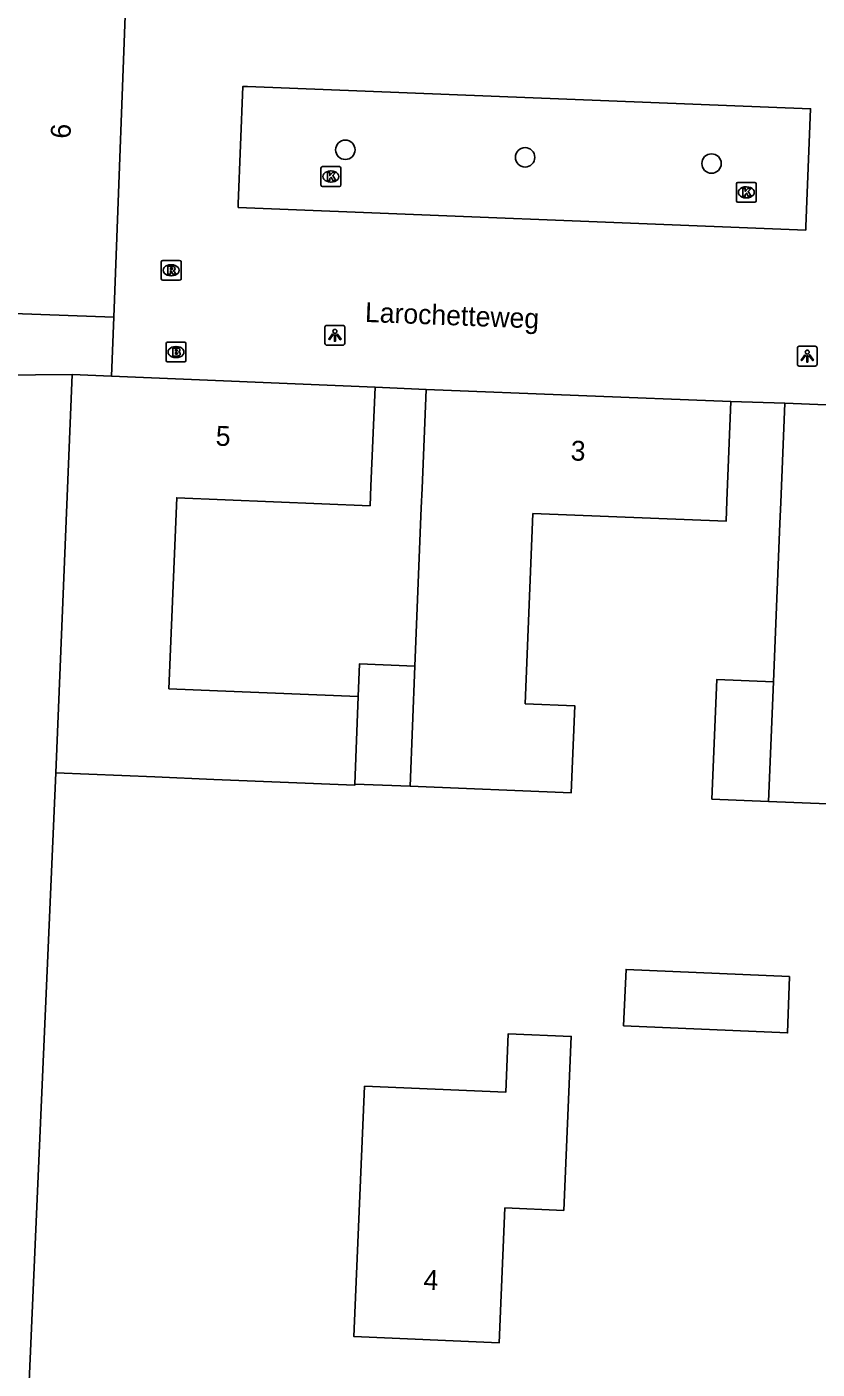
# Model space of a CAD drawing. Extents: x 160787 to 161428, y 386828 to 387483.
# Drawn here: x 160869.9 to 160909.7, y 387090.3 to 387157.9 of the extents above; entities that cross this region are included whole.
import ezdxf

# ---------------------------------------------------------------- set-up
doc = ezdxf.new("R2010")
doc.units = 0
for name, color, linetype in [('IMGEO_Boom', 7, 'Continuous'), ('IMGEO_Brandkraan', 7, 'Continuous'), ('IMGEO_Groenvoorziening', 7, 'Continuous'), ('IMGEO_Kolk', 7, 'Continuous'), ('IMGEO_Lichtpunt', 7, 'Continuous'), ('IMGEO_Openbare_ruimte_label', 7, 'Continuous'), ('IMGEO_Pand', 7, 'Continuous'), ('IMGEO_Pand_nummerreeks', 7, 'Continuous'), ('IMGEO_Rijbaan_lokaal_open', 7, 'Continuous'), ('IMGEO_Rioolput', 7, 'Continuous'), ('IMGEO_Voetpad_open', 7, 'Continuous')]:
    doc.layers.add(name, color=color, linetype=linetype)

msp = doc.modelspace()

# ---------------------------------------------------------------- linework, layer by layer
at = {"layer": 'IMGEO_Boom'}
for centre in [(160885.959, 387151.72), (160895.014, 387151.341), (160904.402, 387151.03)]:
    msp.add_circle(centre, 0.489, dxfattribs=at)
at = {"layer": 'IMGEO_Brandkraan'}
for p, q in [((160877.007, 387142.028), (160877.859, 387142.028)), ((160876.932, 387141.102), (160876.932, 387141.954)), ((160877.42, 387141.808), (160877.445, 387141.808)), ((160877.933, 387141.954), (160877.933, 387141.102)), ((160877.859, 387141.028), (160877.007, 387141.028)), ((160877.443, 387141.248), (160877.418, 387141.248))]:
    msp.add_line(p, q, dxfattribs=at)
for points in [[(160877.007, 387142.028), (160877.859, 387142.028)], [(160876.932, 387141.102), (160876.932, 387141.954)], [(160877.28, 387141.728), (160877.28, 387141.328), (160877.493, 387141.328)], [(160877.511, 387141.728), (160877.28, 387141.728)], [(160877.459, 387141.647), (160877.405, 387141.647), (160877.405, 387141.571)], [(160877.405, 387141.571), (160877.458, 387141.571)], [(160877.467, 387141.495), (160877.405, 387141.495), (160877.405, 387141.414)], [(160877.405, 387141.414), (160877.467, 387141.414)], [(160877.933, 387141.954), (160877.933, 387141.102)], [(160877.859, 387141.028), (160877.007, 387141.028)]]:
    msp.add_lwpolyline(points, dxfattribs=at)
for centre, radius, start, end in [((160877.009, 387141.952), 0.0765, 91.55205, 178.44795), ((160877.009, 387141.952), 0.0765, 91.55205, 178.44795), ((160877.857, 387141.952), 0.0765, 1.55205, 88.44795), ((160877.857, 387141.952), 0.0765, 1.55205, 88.44795), ((160877.46, 387141.609), 0.0379, 267.82845, 90.93552), ((160877.468, 387141.454), 0.0404, 269.87594, 90.50774), ((160877.499, 387141.579), 0.251, 268.66757, 293.53466), ((160877.515, 387141.583), 0.145, 59.4692, 91.53667), ((160877.54, 387141.63), 0.0922, 285.51372, 58.15012), ((160877.545, 387141.438), 0.105, 301.31148, 78.98903), ((160877.009, 387141.104), 0.0765, 181.55205, 268.44795), ((160877.009, 387141.104), 0.0765, 181.55205, 268.44795), ((160877.857, 387141.104), 0.0765, 271.55205, 358.44795), ((160877.857, 387141.104), 0.0765, 271.55205, 358.44795)]:
    msp.add_arc(centre, radius, start, end, dxfattribs=at)
for centre, major_axis, ratio, start_param, end_param in [((160877.419, 387141.528), (-0.387, 0.002), 0.722429, 4.712389, 7.853982), ((160877.444, 387141.528), (-0.39, 0.002), 0.717154, 1.570796, 4.712389)]:
    msp.add_ellipse(centre, major_axis=major_axis, ratio=ratio, start_param=start_param, end_param=end_param, dxfattribs=at)
at = {"layer": 'IMGEO_Groenvoorziening'}
msp.add_lwpolyline([(160871.373, 387120.32), (160870.03, 387089.654)], dxfattribs=at)
at = {"layer": 'IMGEO_Kolk'}
for p, q in [((160884.733, 387149.947), (160884.733, 387150.799)), ((160884.808, 387150.873), (160885.66, 387150.873)), ((160885.734, 387150.799), (160885.734, 387149.947)), ((160885.221, 387150.653), (160885.246, 387150.653)), ((160885.66, 387149.873), (160884.808, 387149.873)), ((160885.244, 387150.093), (160885.219, 387150.093)), ((160905.653, 387149.15), (160905.653, 387150.002)), ((160905.728, 387150.076), (160906.58, 387150.076)), ((160906.141, 387149.856), (160906.166, 387149.856)), ((160906.654, 387150.002), (160906.654, 387149.15)), ((160906.58, 387149.076), (160905.728, 387149.076)), ((160906.164, 387149.296), (160906.139, 387149.296))]:
    msp.add_line(p, q, dxfattribs=at)
for points in [[(160884.733, 387149.947), (160884.733, 387150.799)], [(160884.808, 387150.873), (160885.66, 387150.873)], [(160885.734, 387150.799), (160885.734, 387149.947)], [(160885.054, 387150.573), (160885.177, 387150.573), (160885.177, 387150.422), (160885.307, 387150.573), (160885.471, 387150.573), (160885.325, 387150.422), (160885.478, 387150.173), (160885.326, 387150.173), (160885.241, 387150.337), (160885.177, 387150.27), (160885.177, 387150.173), (160885.054, 387150.173), (160885.054, 387150.573)], [(160885.66, 387149.873), (160884.808, 387149.873)], [(160905.653, 387149.15), (160905.653, 387150.002)], [(160905.728, 387150.076), (160906.58, 387150.076)], [(160905.974, 387149.776), (160906.097, 387149.776), (160906.097, 387149.625), (160906.227, 387149.776), (160906.391, 387149.776), (160906.245, 387149.625), (160906.398, 387149.376), (160906.246, 387149.376), (160906.161, 387149.54), (160906.097, 387149.473), (160906.097, 387149.376), (160905.974, 387149.376), (160905.974, 387149.776)], [(160906.654, 387150.002), (160906.654, 387149.15)], [(160906.58, 387149.076), (160905.728, 387149.076)]]:
    msp.add_lwpolyline(points, dxfattribs=at)
for centre, start, end in [((160884.81, 387150.797), 91.55205, 178.44795), ((160884.81, 387150.797), 91.55205, 178.44795), ((160885.658, 387150.797), 1.55205, 88.44795), ((160885.658, 387150.797), 1.55205, 88.44795), ((160884.81, 387149.949), 181.55205, 268.44795), ((160884.81, 387149.949), 181.55205, 268.44795), ((160885.658, 387149.949), 271.55205, 358.44795), ((160885.658, 387149.949), 271.55205, 358.44795), ((160905.73, 387150), 91.55205, 178.44795), ((160905.73, 387150), 91.55205, 178.44795), ((160906.578, 387150), 1.55205, 88.44795), ((160906.578, 387150), 1.55205, 88.44795), ((160905.73, 387149.152), 181.55205, 268.44795), ((160905.73, 387149.152), 181.55205, 268.44795), ((160906.578, 387149.152), 271.55205, 358.44795), ((160906.578, 387149.152), 271.55205, 358.44795)]:
    msp.add_arc(centre, 0.0765, start, end, dxfattribs=at)
for centre, major_axis, ratio, start_param, end_param in [((160885.22, 387150.373), (-0.387, 0.002), 0.722429, 4.712389, 7.853982), ((160885.245, 387150.373), (-0.39, 0.002), 0.717154, 1.570796, 4.712389), ((160906.14, 387149.576), (-0.387, 0.002), 0.722429, 4.712389, 7.853982), ((160906.165, 387149.576), (-0.39, 0.002), 0.717154, 1.570796, 4.712389)]:
    msp.add_ellipse(centre, major_axis=major_axis, ratio=ratio, start_param=start_param, end_param=end_param, dxfattribs=at)
at = {"layer": 'IMGEO_Lichtpunt'}
for p, q in [((160884.936, 387142.775), (160884.936, 387141.968)), ((160884.936, 387142.775), (160884.936, 387141.968)), ((160885.838, 387142.87), (160885.03, 387142.87)), ((160885.838, 387142.87), (160885.03, 387142.87)), ((160885.932, 387141.968), (160885.932, 387142.775)), ((160885.932, 387141.968), (160885.932, 387142.775)), ((160885.03, 387141.874), (160885.838, 387141.874)), ((160885.03, 387141.874), (160885.838, 387141.874)), ((160908.725, 387141.726), (160908.725, 387140.919)), ((160908.725, 387141.726), (160908.725, 387140.919)), ((160909.627, 387141.821), (160908.819, 387141.821)), ((160909.627, 387141.821), (160908.819, 387141.821)), ((160909.721, 387140.919), (160909.721, 387141.726)), ((160909.721, 387140.919), (160909.721, 387141.726)), ((160908.819, 387140.825), (160909.627, 387140.825)), ((160908.819, 387140.825), (160909.627, 387140.825))]:
    msp.add_line(p, q, dxfattribs=at)
for points in [[(160885.31, 387142.439), (160885.349, 387142.411), (160885.161, 387142.149), (160885.123, 387142.176), (160885.31, 387142.439)], [(160885.412, 387142.391), (160885.459, 387142.391), (160885.459, 387142.069), (160885.412, 387142.069), (160885.412, 387142.391)], [(160885.522, 387142.411), (160885.56, 387142.438), (160885.747, 387142.176), (160885.708, 387142.148), (160885.522, 387142.411)], [(160909.099, 387141.39), (160909.138, 387141.362), (160908.95, 387141.1), (160908.912, 387141.127), (160909.099, 387141.39)], [(160909.201, 387141.342), (160909.248, 387141.342), (160909.248, 387141.02), (160909.201, 387141.02), (160909.201, 387141.342)], [(160909.311, 387141.362), (160909.349, 387141.389), (160909.536, 387141.127), (160909.497, 387141.099), (160909.311, 387141.362)]]:
    msp.add_lwpolyline(points, dxfattribs=at)
for centre in [(160885.435, 387142.573), (160909.224, 387141.524)]:
    msp.add_circle(centre, 0.0994, dxfattribs=at)
for centre, start, end in [((160885.03, 387142.775), 90, 180), ((160885.03, 387142.775), 90, 180), ((160885.838, 387142.775), 0, 90), ((160885.838, 387142.775), 0, 90), ((160885.03, 387141.968), 180, 270), ((160885.03, 387141.968), 180, 270), ((160885.838, 387141.968), 270, 0), ((160885.838, 387141.968), 270, 360), ((160908.819, 387141.726), 90, 180), ((160908.819, 387141.726), 90, 180), ((160909.627, 387141.726), 0, 90), ((160909.627, 387141.726), 0, 90), ((160908.819, 387140.919), 180, 270), ((160908.819, 387140.919), 180, 270), ((160909.627, 387140.919), 270, 0), ((160909.627, 387140.919), 270, 360)]:
    msp.add_arc(centre, 0.0946, start, end, dxfattribs=at)
at = {"layer": 'IMGEO_Pand'}
for points in [[(160874.993, 387161.62), (160874.296, 387143.28)], [(160874.296, 387143.28), (160868.308, 387143.505)], [(160872.202, 387140.397), (160871.373, 387120.32)], [(160872.202, 387140.397), (160874.183, 387140.315)], [(160874.183, 387140.315), (160887.456, 387139.767)], [(160887.456, 387139.767), (160887.25, 387134.772), (160887.209, 387133.784), (160877.47, 387134.186), (160877.073, 387124.564), (160879.525, 387124.462), (160886.608, 387124.167)], [(160889.468, 387125.699), (160889.786, 387133.678), (160889.825, 387134.648), (160890.025, 387139.644)], [(160890.025, 387139.644), (160905.377, 387139.03)], [(160905.377, 387139.03), (160905.177, 387134.034), (160905.136, 387133.002), (160895.404, 387133.391), (160895.022, 387123.808), (160897.516, 387123.708), (160897.341, 387119.319), (160889.219, 387119.644)], [(160907.527, 387124.913), (160907.846, 387132.894), (160907.888, 387133.955), (160908.088, 387138.951)], [(160908.088, 387138.951), (160923.499, 387138.336)], [(160923.499, 387138.336), (160923.255, 387132.223), (160913.4, 387132.617), (160913.018, 387123.053), (160915.51, 387122.953), (160915.335, 387118.564), (160907.279, 387118.886)], [(160889.468, 387125.699), (160886.673, 387125.811), (160886.608, 387124.167)], [(160889.219, 387119.644), (160889.468, 387125.699)], [(160907.279, 387118.886), (160904.425, 387119), (160904.666, 387125.027), (160907.527, 387124.913)], [(160907.527, 387124.913), (160907.279, 387118.886)], [(160886.608, 387124.167), (160886.433, 387119.755)], [(160886.433, 387119.755), (160886.431, 387119.698), (160879.341, 387119.991), (160876.369, 387120.114), (160871.373, 387120.32)], [(160889.219, 387119.644), (160886.433, 387119.755)], [(160908.325, 387110.057), (160908.232, 387107.216), (160899.975, 387107.575), (160900.099, 387110.415), (160908.325, 387110.057)], [(160896.964, 387098.271), (160893.996, 387098.397), (160893.709, 387091.605), (160886.394, 387091.914), (160886.929, 387104.53), (160894.041, 387104.229), (160894.166, 387107.174), (160897.335, 387107.04), (160896.964, 387098.271)]]:
    msp.add_lwpolyline(points, dxfattribs=at)
at = {"layer": 'IMGEO_Rijbaan_lokaal_open'}
for points in [[(160880.561, 387148.813), (160880.569, 387148.998), (160880.804, 387154.919), (160881.034, 387154.909), (160909.388, 387153.789), (160909.153, 387147.862), (160909.145, 387147.677), (160880.561, 387148.813)], [(160874.183, 387140.315), (160874.296, 387143.28)], [(160887.456, 387139.767), (160890.025, 387139.644)], [(160908.088, 387138.951), (160905.377, 387139.03)]]:
    msp.add_lwpolyline(points, dxfattribs=at)
at = {"layer": 'IMGEO_Rioolput'}
for p, q in [((160876.688, 387145.224), (160876.688, 387146.076)), ((160876.763, 387146.15), (160877.615, 387146.15)), ((160877.689, 387146.076), (160877.689, 387145.224)), ((160877.199, 387145.37), (160877.174, 387145.37)), ((160877.176, 387145.93), (160877.201, 387145.93)), ((160877.615, 387145.15), (160876.763, 387145.15))]:
    msp.add_line(p, q, dxfattribs=at)
for points in [[(160876.688, 387145.224), (160876.688, 387146.076)], [(160876.763, 387146.15), (160877.615, 387146.15)], [(160877.689, 387146.076), (160877.689, 387145.224)], [(160877.277, 387145.848), (160877.025, 387145.85), (160877.025, 387145.45)], [(160877.025, 387145.45), (160877.149, 387145.45), (160877.149, 387145.612), (160877.16, 387145.612)], [(160877.203, 387145.769), (160877.149, 387145.769), (160877.149, 387145.688)], [(160877.149, 387145.688), (160877.201, 387145.688)], [(160877.207, 387145.583), (160877.278, 387145.45), (160877.418, 387145.45), (160877.353, 387145.576)], [(160877.615, 387145.15), (160876.763, 387145.15)]]:
    msp.add_lwpolyline(points, dxfattribs=at)
for centre, radius, start, end in [((160876.765, 387146.074), 0.0765, 91.55205, 178.44795), ((160876.765, 387146.074), 0.0765, 91.55205, 178.44795), ((160877.613, 387146.074), 0.0765, 1.55205, 88.44795), ((160877.613, 387146.074), 0.0765, 1.55205, 88.44795), ((160877.159, 387145.559), 0.0533, 26.02933, 88.69889), ((160877.185, 387145.877), 0.19, 274.7715, 282.96867), ((160877.209, 387145.673), 0.0964, 77.00612, 93.18647), ((160877.223, 387145.73), 0.0378, 276.66336, 79.67722), ((160877.276, 387145.738), 0.109, 350.36119, 89.41601), ((160877.274, 387145.738), 0.112, 277.58423, 350.98172), ((160877.258, 387145.523), 0.108, 29.51342, 73.79051), ((160876.765, 387145.226), 0.0765, 181.55205, 268.44795), ((160876.765, 387145.226), 0.0765, 181.55205, 268.44795), ((160877.613, 387145.226), 0.0765, 271.55205, 358.44795), ((160877.613, 387145.226), 0.0765, 271.55205, 358.44795)]:
    msp.add_arc(centre, radius, start, end, dxfattribs=at)
for centre, major_axis, ratio, start_param, end_param in [((160877.175, 387145.65), (-0.387, 0.002), 0.722429, 4.712389, 7.853982), ((160877.2, 387145.65), (-0.39, 0.002), 0.717154, 1.570796, 4.712389)]:
    msp.add_ellipse(centre, major_axis=major_axis, ratio=ratio, start_param=start_param, end_param=end_param, dxfattribs=at)
at = {"layer": 'IMGEO_Voetpad_open'}
msp.add_lwpolyline([(160868.486, 387140.358), (160872.202, 387140.397)], dxfattribs=at)

# ---------------------------------------------------------------- texts
at = {"layer": 'IMGEO_Openbare_ruimte_label'}
msp.add_text('Larochetteweg', height=1, rotation=357.82163, dxfattribs=at).set_placement((160886.937, 387143.047))
at = {"layer": 'IMGEO_Pand_nummerreeks'}
for s, rotation, p in [('6', 87.82356, (160872.116, 387152.27)), ('5', 357.63368, (160879.418, 387136.816)), ('3', 357.70969, (160897.295, 387136.07)), ('4', 357.58115, (160889.883, 387094.289))]:
    msp.add_text(s, height=1, rotation=rotation, dxfattribs=at).set_placement(p)

doc.saveas('drawing.dxf')
